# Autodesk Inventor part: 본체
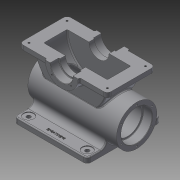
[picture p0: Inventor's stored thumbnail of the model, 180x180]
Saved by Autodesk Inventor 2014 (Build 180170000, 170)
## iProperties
Created: 2023-06
Part Number: 본체
Material: 알루미늄 6061
Document SubType Name: Modeling
Designer: mdu-01
Mass: 5748.39 g
Surface Area: 2841.69 cm^2
Volume: 2121.18 cm^3
Density: 2.71 g/cm^3
Appearance: 알루미늄 - 평지
Author: mdu-01
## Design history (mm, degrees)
sketch "스케치1"
  geometry: L1 (0, 70)-(0, -70); L2 (0, 0)-(-100, 0); L3 (0, 70)-(-45, 70); L4 (-45, 70)-(-45, 45); L5 (-45, 45)-(-100, 45); L6 (0, -70)-(-45, -70); L7 (-45, -70)-(-45, -45); L8 (-45, -45)-(-100, -45); L9 (-100, 45)-(-100, -45); 1 further point
  constraints: 18 end point, 3 perpendicular, 3 symmetric about line, 2 midpoint, 2 parallel, 1 coincident, 1 vertical
  dimensions: "d0" = 140 distance of L1.start L1.end; "d1" = 100 distance of L2.start L2.end; "d3" = 90 diameter of L4 L1; "d4" = 90 distance between parallel lines of L8 L5
revolve "회전1" sketch "스케치1" stored, may be unused: angle "d5" = 180 deg
sketch "스케치2"
  geometry: L1 (-155, -20)-(65, -20); L2 (75, -10)-(75, 100); L3 (65, 110)-(-155, 110); L4 (-165, 100)-(-165, -10); L5 (-165, -20)-(75, 110); L6 (75, -20)-(-165, 110); A1 r 10 centre (-155, 100) between (-155, 110) and (-165, 100); A2 r 10 centre (65, 100) between (75, 100) and (65, 110); A3 r 10 centre (65, -10) between (65, -20) and (75, -10); A4 r 10 centre (-155, -10) between (-165, -10) and (-155, -20); 1 further point
  constraints: 12 end point, 8 point on circle, 8 point on line, 8 tangent, 4 centre point, 3 equal radius, 2 midpoint, 2 parallel, 1 horizontal, 1 perpendicular
  dimensions: "d6" = 240 distance of L6.end L5.end; "d7" = 130 distance of L5.end L6.start; "d8" = 10 radius of A1
extrude "돌출1" join sketch "스케치2" distance "d9" = 15; taper "d10" = 0 deg
sketch "스케치3"
  geometry: C1 r 55 at (-100, 0); 1 further point
  constraints: 1 centre point
  dimensions: "d11" = 110 diameter of C1; "d12" = 100 distance of C1.centre point (0, 0)
extrude "돌출2" join sketch "스케치3" distance "d13" = 135; taper "d15" = 0 deg; dims "d14" = 107, "d16" = 0
sketch "스케치4"
  geometry: L1 (-100, -160)-(100, -160); L2 (100, -160)-(100, -145); L3 (100, -145)-(-100, -145); L4 (-100, -145)-(-100, -160); 1 further point
  constraints: 8 end point, 2 parallel, 1 horizontal, 1 perpendicular
  dimensions: "d17" = 200 distance of L3.end L2.end; "d18" = 15 distance of L2.end L1.end; "d19" = 100 distance from line of L4 point (0, 0); "d20" = 160 distance from line of L1 point (0, 0)
extrude "돌출3" join sketch "스케치4" stored distance "d21" = 200; taper "d22" = 0 deg
fillet "모깎기1" dims "d23" = 15
fillet "모깎기2" dims "d24" = 10
sketch "스케치5"
  geometry: L1 (0, 70)-(0, -70); L2 (-45, 70)-(0, 70) reference; L3 (-45, -70)-(0, -70) reference; L4 (-31, 70)-(-31, 48); L5 (-30, 47)-(-27.5, 47); L6 (-27.5, 47)-(-27.5, 32); L7 (-27.5, 32)-(-87, 32); L8 (0, 0)-(-91.923, 0); L9 (-31, -70)-(-31, -48); L10 (-30, -47)-(-27.5, -47); L11 (-27.5, -47)-(-27.5, -32); L12 (-27.5, -32)-(-87, -32); L13 (-87, 32)-(-87, -32); L14 (-31, 70)-(0, 70); L15 (-31, -70)-(0, -70); A1 r 1 centre (-30, 48) between (-31, 48) and (-30, 47); A2 r 1 centre (-30, -48) between (-30, -47) and (-31, -48)
  constraints: 26 end point, 7 symmetric about line, 4 parallel, 4 point on circle, 3 perpendicular, 2 centre point, 2 tangent, 1 collinear, 1 point on line, 1 vertical, 1 other
  dimensions: "d25" = 1 radius of A1; "d26" = 62 diameter of L4 L1; "d27" = 23 distance between parallel lines of L2 L5; "d28" = 64 distance between parallel lines of L12 L7; "d29" = 55 diameter of L6 L1; "d30" = 87 distance between parallel lines of L13 L1
revolve "회전2" sketch "스케치5" stored, may be unused: angle "d31" = 180 deg
sketch "스케치6"
  geometry: L1 (-107, -45)-(-107, -155) reference; L2 (135, -155)-(135, -45) reference; L3 (-107, -100)-(135, -100); L4 (-107, -142.5)-(-83.1, -142.5); L5 (-82, -141.4)-(-82, -138.5); L6 (-82, -138.5)-(110, -138.5); L7 (110, -138.5)-(110, -141.4); L8 (111.1, -142.5)-(135, -142.5); A1 r 1.1 centre (-83.1, -141.4) between (-83.1, -142.5) and (-82, -141.4); A2 r 1.1 centre (111.1, -141.4) between (110, -141.4) and (111.1, -142.5); 1 further point
  constraints: 12 end point, 4 point on circle, 4 tangent, 3 parallel, 2 centre point, 2 collinear, 2 midpoint, 2 perpendicular, 2 point on line, 1 equal radius
  dimensions: "d32" = 1.1 radius of A1; "d33" = 25 distance between parallel lines of L5 L1; "d34" = 77 diameter of L6 L3; "d35" = 85 diameter of L4 L3
revolve "회전3" sketch "스케치6" stored, may be unused: angle "d36" = 180 deg
fillet "모깎기3" dims "d37" = 3
fillet "모깎기4" dims "d38" = 3
sketch "스케치7"
  geometry: L1 (17, -16.754)-(177, -16.754); L2 (177, -16.754)-(177, 143.246); L3 (177, 143.246)-(17, 143.246); L4 (17, 143.246)-(17, -16.754); L5 (17, -16.754)-(177, 143.246); L6 (177, -16.754)-(17, 143.246); 1 further point
  constraints: 12 end point, 2 midpoint, 2 parallel, 1 horizontal, 1 perpendicular
  dimensions: "d39" = 160 distance of L3.end L2.end; "d40" = 160 distance of L2.end L1.end
hole "구멍1" sketch "스케치7" at (17, -16.754), (177, -16.754), (177, 143.246), (17, 143.246) diameter "d41" = 11; stored, may be unused: countersink angle "d45" = 90 deg, drill point angle "d47" = 118 deg; dims "d42" = 6, "d43" = 28, "d44" = 2, "d46" = 8
sketch "스케치8"
  geometry: L1 (-227, 3)-(-13, 3); L2 (-13, 3)-(-13, 107); L3 (-13, 107)-(-227, 107); L4 (-227, 107)-(-227, 3); L5 (-227, 3)-(-13, 107); L6 (-13, 3)-(-227, 107); 1 further point
  constraints: 12 end point, 2 midpoint, 2 parallel, 1 horizontal, 1 perpendicular
  dimensions: "d48" = 214 distance of L3.end L2.end; "d49" = 104 distance of L2.end L1.end
hole "구멍2" sketch "스케치8" at (-227, 3), (-13, 3), (-13, 107), (-227, 107) diameter "d50" = 4.917; stored, may be unused: countersink angle "d54" = 90 deg, drill point angle "d56" = 118 deg; dims "d51" = 15, "d52" = 4, "d53" = 7.5, "d55" = 15
sketch "스케치9"
  geometry: A1 r 37 centre (0, 0) between (-26.163, -26.163) and (26.163, -26.163); 1 further point
  constraints: 2 point on circle, 1 centre point, 1 coincident, 1 horizontal alignment
  dimensions: "d57" = 37 radius of A1; "d58" = 90 deg dimension on A1.centre A1.end A1.start
hole "구멍3" sketch "스케치9" at (-26.163, -26.163), (26.163, -26.163) diameter "d60" = 4.134; stored, may be unused: countersink angle "d64" = 90 deg, drill point angle "d66" = 118 deg; dims "d61" = 10, "d62" = 4, "d63" = 7.5, "d65" = 12
sketch "스케치10" dims "d68" = 97
  geometry: C1 r 38.5 at (0, 0) reference; 3 further points
  constraints: 2 vertical alignment, 1 coincident, 2 other
hole "구멍4" sketch "스케치10" at (0, 48.5) diameter "d70" = 4.134; stored, may be unused: countersink angle "d74" = 90 deg, drill point angle "d76" = 118 deg; dims "d71" = 10, "d72" = 4, "d73" = 7.5, "d75" = 12
node "작업 평면1"
sketch "스케치11"
  geometry: L1 (7, -36.754)-(187, -36.754) reference; 2 further points
  constraints: 1 vertical alignment, 1 other
  dimensions: "d80" = 15 distance from line of point (97, -21.754) L1
feature "엠보싱1" sketch "스케치11" dims "d0" = 140, "d1" = 100, "d3" = 90, "d4" = 90, "d6" = 240, "d7" = 130, "d8" = 10, "d81" = 0.5, "d82" = 0
chamfer "모따기1" distance "d83" = 1; stored, may be unused: second distance "d84" = 2, angle "d85" = 45 deg
node "솔리드1"
mirror "대칭1"
pattern_circular "원형 패턴1" dims angle "d78" = 360 deg
mirror "대칭2"
